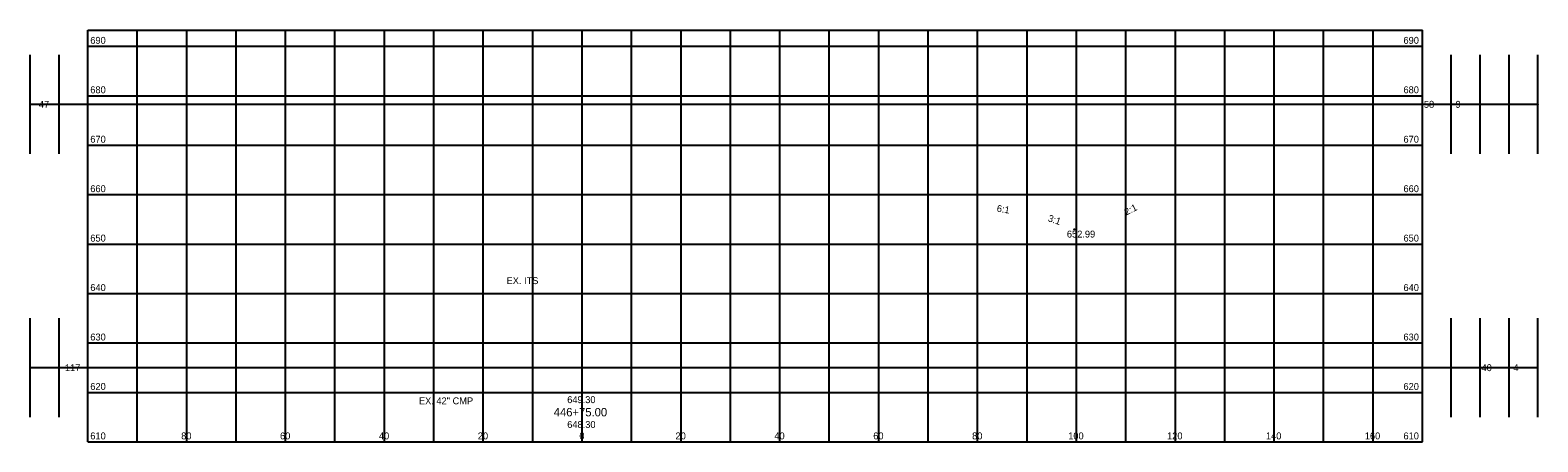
# Model space of a CAD drawing. Extents: x -112 to 193, y 610 to 693.
import ezdxf

# ---------------------------------------------------------------- set-up
doc = ezdxf.new("R2010")
doc.units = 0
for name, color, linetype in [('_CIVIL_CONSTRUCTION', 7, 'Continuous'), ('Default', 7, 'Continuous'), ('GE_X_Alignment_100_Stations', 7, 'Continuous'), ('PF_X_Ground_Line', 7, 'Continuous'), ('RS_Raster1', 7, 'Continuous'), ('SC_Scratch1', 7, 'Continuous'), ('SH_Text', 7, 'Continuous')]:
    doc.layers.add(name, color=color, linetype=linetype)

msp = doc.modelspace()

# ---------------------------------------------------------------- linework, layer by layer
at = {"layer": '_CIVIL_CONSTRUCTION'}
msp.add_circle((99.59, 652.99), 0.05, dxfattribs=at)
at = {"layer": 'Default'}
msp.add_circle((193.33, 678.26), 0.000833, dxfattribs=at)
msp.add_circle((193.33, 678.26), 0.000833, dxfattribs=at)
at = {"layer": 'PF_X_Ground_Line'}
for p, q in [((-100, 693.26), (170, 693.26)), ((-100, 610), (-100, 693.26)), ((-90, 610), (-90, 693.26)), ((-80, 610), (-80, 693.26)), ((-70, 610), (-70, 693.26)), ((-60, 610), (-60, 693.26)), ((-50, 610), (-50, 693.26)), ((-40, 610), (-40, 693.26)), ((-30, 610), (-30, 693.26)), ((-20, 610), (-20, 693.26)), ((-10, 610), (-10, 693.26)), ((0, 610), (0, 693.26)), ((10, 610), (10, 693.26)), ((20, 610), (20, 693.26)), ((30, 610), (30, 693.26)), ((40, 610), (40, 693.26)), ((50, 610), (50, 693.26)), ((60, 610), (60, 693.26)), ((70, 610), (70, 693.26)), ((80, 610), (80, 693.26)), ((90, 610), (90, 693.26)), ((100, 610), (100, 693.26)), ((110, 610), (110, 693.26)), ((120, 610), (120, 693.26)), ((130, 610), (130, 693.26)), ((140, 610), (140, 693.26)), ((150, 610), (150, 693.26)), ((160, 610), (160, 693.26)), ((170, 610), (170, 693.26)), ((-100, 690), (170, 690)), ((-100, 680), (170, 680)), ((-100, 670), (170, 670)), ((-100, 660), (170, 660)), ((-100, 650), (170, 650)), ((-100, 640), (170, 640)), ((-100, 630), (170, 630)), ((-100, 620), (170, 620)), ((-100, 610), (170, 610))]:
    msp.add_line(p, q, dxfattribs=at)
at = {"layer": 'RS_Raster1'}
for p, q in [((-108.75, 678.26), (-108.75, 678.26)), ((172.92, 678.26), (172.92, 678.26)), ((178.75, 678.26), (178.75, 678.26)), ((-102.92, 625), (-102.92, 625))]:
    msp.add_line(p, q, dxfattribs=at)
at = {"layer": 'SC_Scratch1'}
for p, q in [((-111.67, 668.26), (-111.67, 688.26)), ((-105.83, 668.26), (-105.83, 688.26)), ((-100, 668.26), (-100, 688.26)), ((170, 668.26), (170, 688.26)), ((175.83, 668.26), (175.83, 688.26)), ((181.67, 668.26), (181.67, 688.26)), ((187.5, 668.26), (187.5, 688.26)), ((193.33, 668.26), (193.33, 688.26)), ((193.33, 678.26), (-111.67, 678.26)), ((-111.67, 615), (-111.67, 635)), ((-105.83, 615), (-105.83, 635)), ((-100, 615), (-100, 635)), ((170, 615), (170, 635)), ((175.83, 615), (175.83, 635)), ((181.67, 615), (181.67, 635)), ((187.5, 615), (187.5, 635)), ((193.33, 615), (193.33, 635)), ((193.33, 625), (-111.67, 625)), ((184.59, 625), (184.59, 625)), ((190.41, 625), (190.41, 625))]:
    msp.add_line(p, q, dxfattribs=at)

# ---------------------------------------------------------------- texts
at = {"layer": 'GE_X_Alignment_100_Stations'}
for s, p in [('EX. ITS', (-15.29, 641.9)), ('EX. 42" CMP', (-33.02, 617.59))]:
    msp.add_text(s, height=1.4, dxfattribs=at).set_placement(p)
at = {"layer": 'SH_Text'}
for s, height, p in [('690', 1.4, (-99.5, 690.5)), ('690', 1.4, (166.15, 690.5)), ('680', 1.4, (-99.5, 680.5)), ('680', 1.4, (166.15, 680.5)), ('47', 1.4, (-109.9, 677.56)), ('58', 1.4, (170.28, 677.56)), ('9', 1.4, (176.68, 677.56)), ('670', 1.4, (-99.5, 670.5)), ('670', 1.4, (166.15, 670.5)), ('660', 1.4, (-99.5, 660.5)), ('660', 1.4, (166.15, 660.5)), ('652.99', 1.4, (98.06, 651.32)), ('650', 1.4, (-99.5, 650.5)), ('650', 1.4, (166.15, 650.5)), ('640', 1.4, (-99.5, 640.5)), ('640', 1.4, (166.15, 640.5)), ('630', 1.4, (-99.5, 630.5)), ('630', 1.4, (166.15, 630.5)), ('117', 1.4, (-104.63, 624.3)), ('40', 1.4, (181.94, 624.3)), ('4', 1.4, (188.37, 624.3)), ('620', 1.4, (-99.5, 620.5)), ('649.30', 1.4, (-3.02, 617.83)), ('620', 1.4, (166.15, 620.5)), ('446+75.00', 1.7, (-5.75, 615.15)), ('648.30', 1.4, (-3.02, 612.8)), ('610', 1.4, (-99.5, 610.5)), ('80', 1.4, (-81.11, 610.5)), ('60', 1.4, (-61.11, 610.5)), ('40', 1.4, (-41.11, 610.5)), ('20', 1.4, (-21.11, 610.5)), ('0', 1.4, (-0.56, 610.5)), ('20', 1.4, (18.89, 610.5)), ('40', 1.4, (38.89, 610.5)), ('60', 1.4, (58.89, 610.5)), ('80', 1.4, (78.89, 610.5)), ('100', 1.4, (98.33, 610.5)), ('120', 1.4, (118.33, 610.5)), ('140', 1.4, (138.33, 610.5)), ('160', 1.4, (158.33, 610.5)), ('610', 1.4, (166.15, 610.5))]:
    msp.add_text(s, height=height, dxfattribs=at).set_placement(p)
for s, rotation, p in [('6:1', 350.5358, (83.8, 656.57)), ('3:1', 341.5652, (94.11, 654.65)), ('2:1', 26.5651, (110.1, 655.77))]:
    msp.add_text(s, height=1.4, rotation=rotation, dxfattribs=at).set_placement(p)

doc.saveas('drawing.dxf')
